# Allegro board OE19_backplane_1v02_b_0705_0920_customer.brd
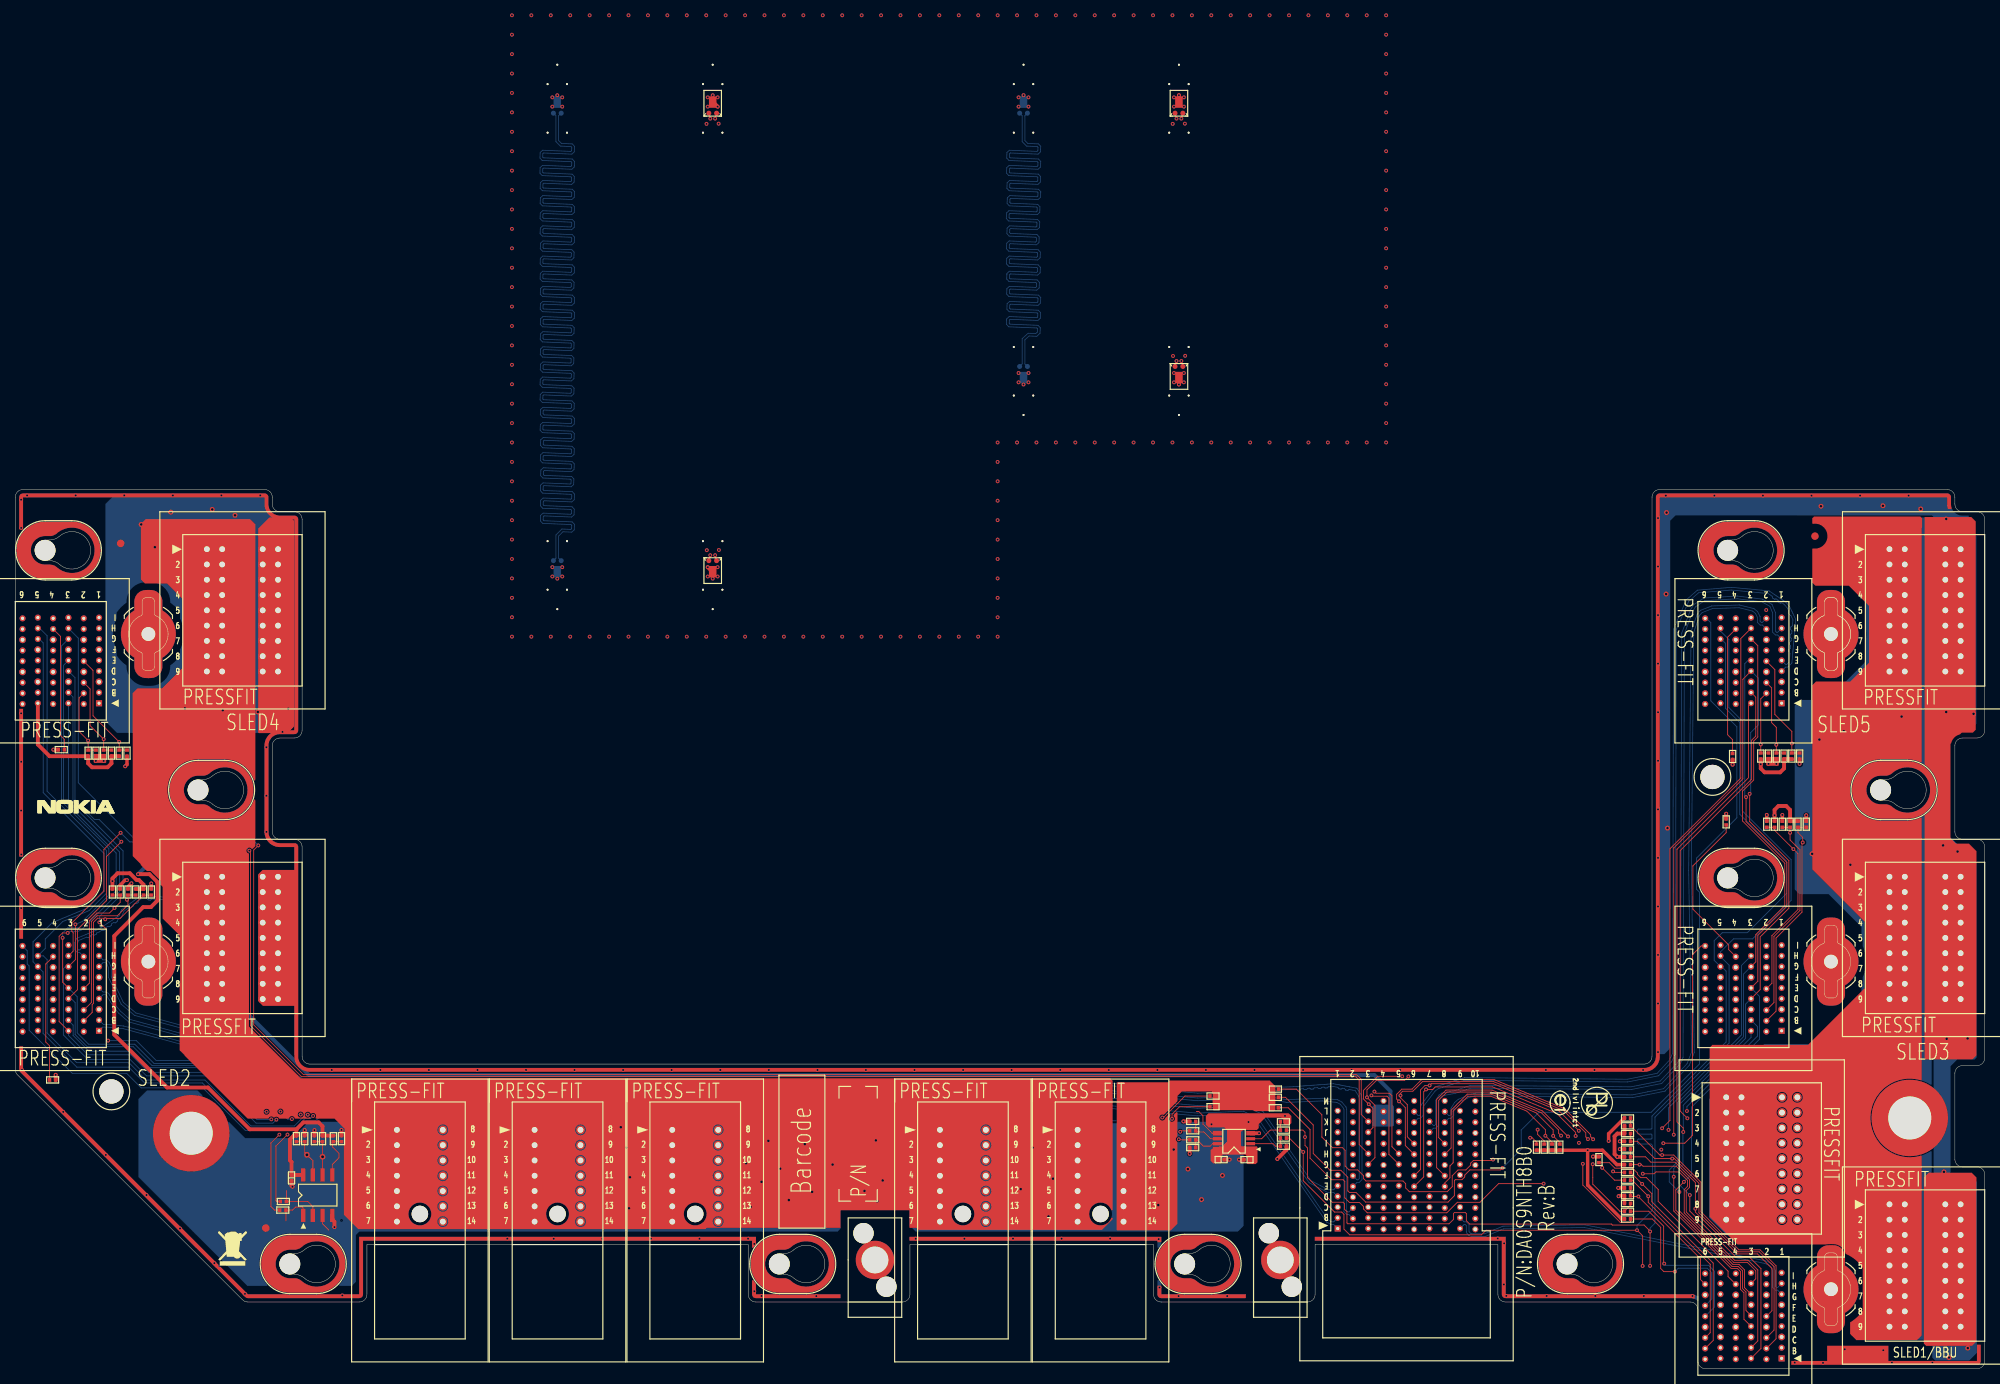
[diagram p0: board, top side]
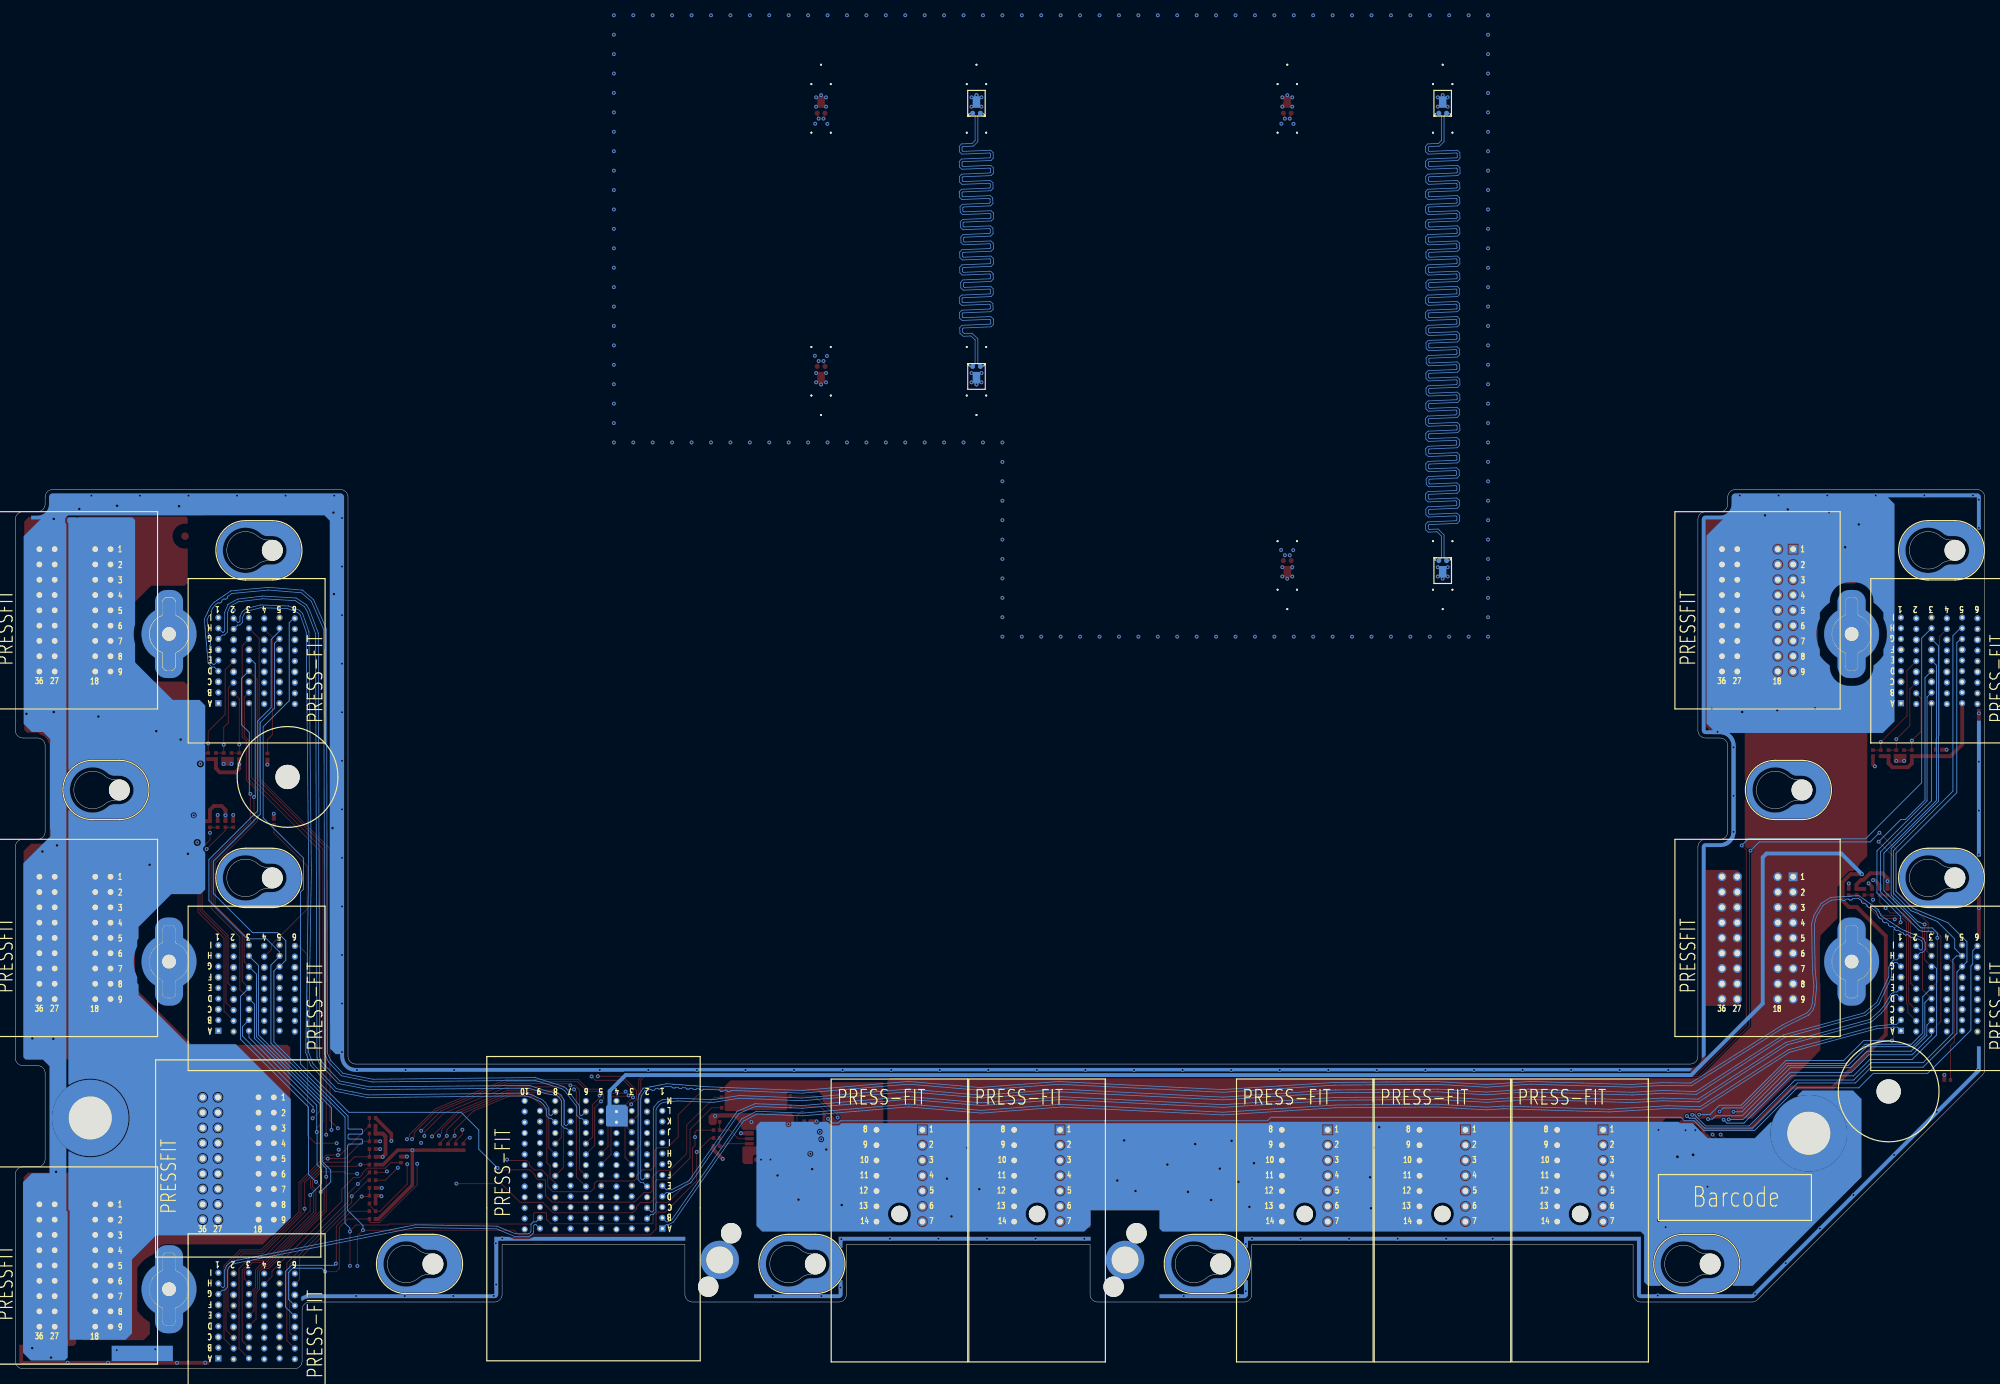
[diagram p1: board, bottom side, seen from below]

Outline 257.5 x 115 mm; copper layers: TOP, GND, IN1, VCC, VCC1, IN2, GND1, BOTTOM. Coordinates in mm from the lower left corner of the outline.

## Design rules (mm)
net group DELTA_L_85_5INCH_BOT_D: nets DELTA_L_85_5INCH_BOT_DN DELTA_L_85_5INCH_BOT_DP
net group DELTA_L_85_5INCH_IN2_D: nets DELTA_L_85_5INCH_IN2_DN DELTA_L_85_5INCH_IN2_DP
net group DELTA_L_85_10INCH_BOT_D: nets DELTA_L_85_10INCH_BOT_DN DELTA_L_85_10INCH_BOT_DP
net group DELTA_L_85_10INCH_IN2_D: nets DELTA_L_85_10INCH_IN2_DN DELTA_L_85_10INCH_IN2_DP
net group SMB_BBU_ALERT_N: nets SMB_BBU_ALERT_N SMB_BBU_ALERT_R_N
net group SMB_PMBUS_BBU_SCL: nets SMB_PMBUS_BBU_SCL SMB_PMBUS_SCL
net group SMB_PMBUS_BBU_SDA: nets SMB_PMBUS_BBU_SDA SMB_PMBUS_SDA
net group SMB_SLED_BUF_SCL: nets SMB_SLED_BUF_SCL SMB_SLED_BUF_SCL_R
net group SMB_SLED_BUF_SDA: nets SMB_SLED_BUF_SDA SMB_SLED_BUF_SDA_R
net group LAN: nets LAN_SLED1_MDIN1 LAN_SLED1_MDIP1 LAN_SLED2_MDIN3 LAN_SLED2_MDIP3 LAN_SLED3_MDIN0 LAN_SLED3_MDIN1 LAN_SLED3_MDIN3 LAN_SLED3_MDIP0 LAN_SLED3_MDIP1 LAN_SLED3_MDIP3 LAN_SLED4_MDIN0 LAN_SLED4_MDIN1 LAN_SLED4_MDIN2 LAN_SLED4_MDIN3 LAN_SLED4_MDIP0 LAN_SLED4_MDIP1 LAN_SLED4_MDIP2 LAN_SLED4_MDIP3 LAN_SLED5_MDIN0 LAN_SLED5_MDIN1 LAN_SLED5_MDIP0 LAN_SLED5_MDIP1
net group P3V3_SLED1: nets P3V3_SLED1 SB_SLED1_ADDR_0 SB_SLED1_ADDR_1 SB_SLED1_ADDR_2
net group P3V3_SLED2: nets P3V3_SLED2 SB_SLED2_ADDR_0 SB_SLED2_ADDR_1 SB_SLED2_ADDR_2
net group P3V3_SLED3: nets P3V3_SLED3 SB_SLED3_ADDR_0 SB_SLED3_ADDR_1 SB_SLED3_ADDR_2
net group P3V3_SLED4: nets P3V3_SLED4 SB_SLED4_ADDR_0 SB_SLED4_ADDR_1 SB_SLED4_ADDR_2
net group P3V3_SLED5: nets P3V3_SLED5 SB_SLED5_ADDR_0 SB_SLED5_ADDR_1 SB_SLED5_ADDR_2
net group SMB_3UBP_TEMP_SCL: nets SMB_3UBP_TEMP_SCL SMB_SLED_COMBINE_SCL SMB_SLED_COMBINE_SCL_R
net group SMB_3UBP_TEMP_SDA: nets SMB_3UBP_TEMP_SDA SMB_SLED_COMBINE_SDA SMB_SLED_COMBINE_SDA_R

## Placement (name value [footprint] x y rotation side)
C1045  0.1UF  [C0402]  36.12 24.96 270 top
C1375  0.1UF  [C0402]  157.66 27.35 0 top
C1377  0.1UF  [C0402]  161.05 27.34 180 top
DM2  -  [WEEE]  26.73 13.47 0 top
DM3  -  [PB-E1_SMALL]  206.79 34.78 270 top
DM4  -  [PNLABEL_15X5]  112.7 21.92 90 top
DM7  -  [BARCODE_20X6]  42.66 19.4 180 bottom
DM8  -  [BARCODE_20X6]  105.85 18.39 90 top
H1  -  [HOLE_C10D5-6B10_NPB]  247.7 32.8 0 top
H2  -  [HOLE_C10D5-6B10_NPB]  23 30.8 0 top
H3  -  [HOLE_C7-5D2-7_4-9B7-5_OB3-5XC3-75N_NPM]  23.9 75.7 90 top
H4  -  [HOLE_C7-5D2-7_4-9B7-5_OB3-5XC3-75N_NPM]  3.9 107.05 90 top
H5  -  [HOLE_C7-5D2-7_4-9B7-5_OB3-5XC3-75N_NPM]  3.9 64.2 90 top
H6  -  [HOLE_C7-5D2-7_4-9B7-5_OB3-5XC3-75N_NPM]  35.9 13.7 90 top
H7  -  [HOLE_C7-5D2-7_4-9B7-5_OB3-5XC3-75N_NPM]  223.9 107.05 90 top
H8  -  [HOLE_C7-5D2-7_4-9B7-5_OB3-5XC3-75N_NPM]  243.9 75.7 90 top
H9  -  [HOLE_C7-5D2-7_4-9B7-5_OB3-5XC3-75N_NPM]  223.9 64.2 90 top
H10  -  [HOLE_C7-5D2-7_4-9B7-5_OB3-5XC3-75N_NPM]  99.9 13.7 90 top
H11  -  [HOLE_C7-5D2-7_4-9B7-5_OB3-5XC3-75N_NPM]  152.9 13.7 90 top
H12  -  [HOLE_C7-5D2-7_4-9B7-5_OB3-5XC3-75N_NPM]  202.9 13.7 90 top
H13  -  [HOLE_TOOLINGD125N_T2-0]  12.56 36.27 0 top
H14  -  [HOLE_TOOLINGD125N_T2-0]  221.9 77.4 0 top
J1  -  [HSD_F36D9_P2_LUV]  245.05 107.2 0 top
J2  -  [HSD_F36D9_P2_LUV]  245.05 21.5 0 top
J3  -  [HSD_F36D9_P2_LUV]  223.7 35.5 0 top
J4  -  [HSD_F36D9_P2_LUV]  25.05 64.35 0 top
J5  -  [HSD_F36D9_P2_LUV]  245.05 64.35 0 top
J6  -  [HSD_F36D9_P2_LUV]  25.05 107.2 0 top
J7  -  [HSD_F54D6_P2W1-4_RDH]  230.95 1.35 180 top
J8  -  [HSD_M120D10H5D_P2W1-4_LDH]  172.9 18.33 180 top
J9  -  [HSD_F54D6_P2W1-4_RDH]  10.95 44.2 180 top
J10  -  [HSD_F54D6_P2W1-4_RDH]  230.95 44.2 180 top
J11  -  [HSD_F54D6_P2W1-4_RDH]  10.95 87.05 180 top
J12  -  [HSD_F54D6_P2W1-4_RDH]  230.95 87.05 180 top
J15  -  [TRIANG_LAUNCH_3PXA]  131.83 165.53 0 bottom
J16  -  [TRIANG_LAUNCH_3PXA]  152.15 129.79 0 top
J21  -  [TRIANG_LAUNCH_3PXA]  131.82 129.79 180 bottom
J22  -  [TRIANG_LAUNCH_3PXA]  152.14 165.53 180 top
J27  -  [TRIANG_LAUNCH_3PXA]  70.86 104.39 180 bottom
J28  -  [TRIANG_LAUNCH_3PXA]  91.18 165.53 180 top
J33  -  [TRIANG_LAUNCH_3PXA]  70.87 165.53 0 bottom
J34  -  [TRIANG_LAUNCH_3PXA]  91.19 104.39 0 top
J37  -  [CON_GUIDE-M1XE]  17.4 53.25 0 top
J38  -  [CON_GUIDE-M1XE]  17.4 96.1 0 top
J39  -  [CON_GUIDE-M1XE]  237.4 10.4 0 top
J40  -  [CON_GUIDE-M1XE]  237.4 53.25 0 top
J41  -  [CON_GUIDE-M1XE]  237.4 96.1 0 top
JP1  -  [HSD_M14]  85.9 31.24 0 top
JP2  -  [HSD_M14]  120.9 31.24 0 top
JP3  -  [HSD_M14]  67.9 31.24 0 top
JP4  -  [HSD_M14]  138.9 31.24 0 top
JP5  -  [CON_GUIDE-FXC]  112.4 14.23 0 top
JP6  -  [CON_GUIDE-FXC]  165.4 14.23 0 top
JP7  -  [HSD_M14]  49.9 31.24 0 top
NOREF  -  []  260.6 232 0 top
NOREF#2  -  []  202.9 13.7 0 top
NOREF#3  -  []  -10 230 0 top
NOREF#4  -  []  258.5 56.87 270 top
NOREF#5  -  []  99.9 13.7 0 top
NOREF#6  -  []  256.5 0 90 top
NOREF#7  -  []  -2 0 0 top
NOREF#8  -  []  237.4 96.1 0 top
NOREF#9  -  []  72.32 40.85 0 top
NOREF#10  -  []  99.9 13.7 0 top
NOREF#11  -  []  223.9 107.05 0 top
NOREF#12  -  []  0.1 140.72 90 top
NOREF#13  -  []  259.6 177.05 90 top
NOREF#14  -  []  -0.9 232 0 top
NOREF#15  -  []  0 39.14 0 top
NOREF#16  -  []  0 0 0 top
NOREF#17  -  []  71.98 191.15 180 top
NOREF#18  -  []  220.1 174.93 90 top
NOREF#19  -  []  135.48 191.15 180 top
NOREF#20  -  []  0.1 178.82 90 top
NOREF#21  -  []  155.31 224.28 180 top
NOREF#22  -  []  17.4 53.25 0 top
NOREF#23  -  []  0 0 0 top
NOREF#24  -  []  3.9 107.05 0 top
NOREF#25  -  []  223.9 107.05 0 top
NOREF#26  -  []  17.4 96.1 0 top
NOREF#27  -  []  237.4 53.25 0 top
NOREF#28  -  []  220.1 132.28 90 top
NOREF#29  -  []  259.6 134.4 90 top
NOREF#30  -  []  45.6 166.85 90 top
NOREF#31  -  []  3.9 64.2 0 top
NOREF#32  -  []  128.6 15.24 0 top
NOREF#33  -  []  258.5 99.52 270 top
NOREF#34  -  []  38.5 99.72 270 top
NOREF#35  -  []  23.9 75.7 0 top
NOREF#36  -  []  157.13 7.72 0 top
NOREF#37  -  []  243.9 75.7 0 top
NOREF#38  -  []  237.4 53.25 0 top
NOREF#39  -  []  85.95 15.24 0 top
NOREF#40  -  []  19.68 116 180 top
NOREF#41  -  []  202.9 13.7 0 top
NOREF#42  -  []  237.4 10.4 0 top
NOREF#43  -  [unnamed#2]  13.77 107.95 0 top
NOREF#44  -  []  123.12 40.85 0 top
NOREF#45  -  []  213 65.15 270 top
NOREF#46  -  []  38.5 57.07 270 top
NOREF#47  -  []  243.9 75.7 0 top
NOREF#48  -  []  237.4 10.4 0 top
NOREF#49  -  [unnamed#2]  235.31 108.9 0 top
NOREF#50  -  []  199.78 7.72 0 top
NOREF#51  -  []  -1 102.62 90 top
NOREF#52  -  []  256.5 0 90 top
NOREF#53  -  []  23.9 75.7 0 top
NOREF#54  -  []  223.9 64.2 0 top
NOREF#55  -  []  56.28 224.28 180 top
NOREF#56  -  []  186.62 40.85 0 top
NOREF#57  -  []  223.9 64.2 0 top
NOREF#58  -  []  45.6 139.3 270 top
NOREF#59  -  []  406.33 171.42 0 top
NOREF#60  -  []  152.9 13.7 0 top
NOREF#61  -  []  259.5 0 0 top
NOREF#62  -  []  17.4 96.1 0 top
NOREF#63  -  []  287.3 400.43 0 top
NOREF#64  -  []  213 92.7 90 top
NOREF#65  -  []  3.9 64.2 0 top
NOREF#66  -  []  237.4 96.1 0 top
NOREF#67  -  []  236.38 116 0 top
NOREF#68  -  []  3.9 107.05 0 top
NOREF#69  -  [unnamed#2]  32.76 18.4 0 top
NOREF#70  -  []  186.28 191.15 180 top
NOREF#71  -  []  152.9 13.7 0 top
NOREF#72  -  []  17.4 53.25 0 top
NOREF#73  -  []  -1 64.52 90 top
R1  4.7K  [R0402]  15.75 62.36 270 top
R2  4.7K  [R0402]  230.02 71.22 270 top
R3  4.7K  [R0402]  9.53 80.52 90 top
R4  4.7K  [R0402]  231.27 80.14 90 top
R5  4.7K  [R0402]  232.28 80.14 90 top
R6  4.7K  [R0402]  13.59 80.52 90 top
R7  1K  [R0402]  10.54 80.52 270 top
R8  4.7K  [R0402]  16.76 62.36 270 top
R9  1K  [R0402]  17.78 62.36 90 top
R10  4.7K  [R0402]  233.09 71.23 270 top
R11  1K  [R0402]  234.17 71.23 90 top
R12  4.7K  [R0402]  232.05 71.22 270 top
R13  4.7K  [R0402]  210.8 30.76 0 top
R14  4.7K  [R0402]  12.7 62.36 270 top
R15  4.7K  [R0402]  210.8 27.71 0 top
R16  4.7K  [R0402]  228.22 80.14 90 top
R17  1K  [R0402]  229.24 80.14 270 top
R18  4.7K  [R0402]  12.57 80.52 90 top
R19  1K  [R0402]  14.73 62.36 90 top
R20  1K  [R0402]  231.04 71.22 90 top
R21  1K  [R0402]  210.8 29.74 180 top
R22  1K  [R0402]  13.72 62.36 90 top
R23  1K  [R0402]  229 71.22 90 top
R24  1K  [R0402]  210.8 28.73 180 top
R25  1K  [R0402]  230.25 80.14 270 top
R26  1K  [R0402]  11.56 80.52 270 top
R27  1K  [R0402]  233.3 80.14 270 top
R28  1K  [R0402]  14.61 80.52 270 top
R29  4.7K  [R0402]  210.8 19.58 0 top
R30  4.7K  [R0402]  201.94 28.98 90 top
R31  4.7K  [R0402]  210.8 22.63 0 top
R32  1K  [R0402]  210.8 23.65 180 top
R33  4.7K  [R0402]  198.89 28.98 90 top
R34  4.7K  [R0402]  200.92 28.98 90 top
R35  4.7K  [R0402]  199.91 28.98 90 top
R36  4.7K  [R0402]  210.8 26.7 0 top
R37  4.7K  [R0402]  210.8 21.62 0 top
R38  0  [R0402]  210.8 20.6 0 top
R39  0  [R0402]  210.8 25.68 0 top
R40  0  [R0402]  210.8 24.66 0 top
R41  100  [R0402]  164.74 34.13 180 top
R42  100  [R0402]  156.6 34.28 0 top
R43  100  [R0402]  164.76 36.57 180 top
R44  100  [R0402]  156.6 35.67 0 top
R45  100  [R0402]  164.75 35.5 180 top
R46  0  [R0402]  153.95 29.94 0 top
R47  0  [R0402]  153.95 31.12 0 top
R48  4.7K  [R0402]  153.95 28.93 0 top
R49  4.7K  [R0402]  153.95 32.35 0 top
R50  4.7K  [R0402]  165.81 29.1 180 top
R51  4.7K  [R0402]  165.81 32.3 180 top
R52  0  [R0402]  165.81 30.17 0 top
R53  0  [R0402]  165.81 31.21 0 top
R54  0  [R0402]  207.07 27.35 90 top
R55  0  [R0402]  4.88 37.78 0 top
R56  0  [R0402]  223.7 71.53 90 top
R57  0  [R0402]  6.01 80.98 180 top
R58  0  [R0402]  224.54 80.08 270 top
R1102  4.7K  [R0402]  41.59 30.09 270 top
R1103  100  [R0402]  42.65 30.09 90 top
R1108  4.7K  [R0402]  40.17 30.09 270 top
R1109  100  [R0402]  39.11 30.09 90 top
R1113  4.7K  [R0402]  36.76 30.09 270 top
R1114  100  [R0402]  37.84 30.09 90 top
R1122  33.2  [R0402]  34.98 20.75 180 top
R1123  33.2  [R0402]  35.05 21.87 180 top
R2297  4.7K  [R0402]  210.8 31.78 0 top
R2298  1K  [R0402]  210.8 32.79 180 top
U31  -  [SOIC8]  39.54 22.7 90 top
U118  -  [TSSOP8_3XB]  159.35 29.76 180 top

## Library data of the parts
C1045 = Q_CAP: alternate symbols: (C0402_OCTAGONXA); part number: Q_CAP_0402-0.1UF,25V,10%,X7R,CH4104K1B00; tolerance: 10%; signal model: DEFAULT_CAPACITOR_100000pF_2_1
C1375 C1377 = Q_CAP: alternate symbols: (C0402_OCTAGONXA); part number: Q_CAP_0402-0.1UF,25V,10%,X7R,CH4104K1B00; tolerance: 10%
DM2 = DUMMY_SYMBOL: part number: DUMMY_SYMBOL-WEEE,MECH,EMPTY,DUMMY2
DM3 = DUMMY_SYMBOL: part number: DUMMY_SYMBOL-PB-E1_SMALL,MECH,EMPTY,DUMMY3
DM4 = DUMMY_SYMBOL: part number: DUMMY_SYMBOL-PCBA_LABEL_15X5,MECH,MECH,DUMMY4
DM7 DM8 = DUMMY_SYMBOL: part number: DUMMY_SYMBOL-BARCODE_20X6,MECH,MECH,DUMMY15
H1 H2 = HOLE: part number: HOLE_TH-EMPTY,HOLE596
H3-H12 = HOLE: part number: HOLE_TH-EMPTY,HOLE1056
H13 H14 = HOLE: part number: HOLE_TH-EMPTY,DUMMY50
J1-J6 = CONN36_10078768001LHLF: part number: CONN36_10078768001LHLF-CONN36_10078768-001LHLF,THLF,IO,DFHS36FS123
J7 J9-J12 = CONN54_10130665102LF: part number: CONN54_10130665102LF-CONN54_10130665-102LF,THLF,IO,DFHS54FS008
J8 = CONN120_10124150102LF: part number: CONN120_10124150102LF-CONN120_10124150-102LF,THLF,IO,DFHDC0MR005
J15 J16 J21 J22 J27 J28 J33 J34 = DELTA_L: part number: DELTA_L-DELTA-L,THLF,EMPTY,TP24
J37-J41 = CONN1_D11402200000Z1: part number: CONN1_D11402200000Z1-CONN1_D11402-200000-Z1,THLF,IO,DFHD01MS073
JP1-JP4 JP7 = CONN14_10028918001LF: part number: CONN14_10028918001LF-CONN14_10028918001LF,THLF,IO,DFPJ14MR000
JP5 JP6 = CONN1_D11403000A00Z1: part number: CONN1_D11403000A00Z1-CONN1_D11403000A00Z1,THLF,IO,DFHS03FR014
R1 R5 R6 R10 R12 R16 R29 R30 R33-R37 R1102 R1108 R2297 = Q_RES: alternate symbols: (SMR0402AW); part number: Q_RES_0402LF-4.7K,1%,1/16W,CHIP,CS24702FB10; tolerance: 1%; signal model: DEFAULT_RESISTOR_4700OHM_2_1
R2-R4 R8 R13-R15 R18 R31 R1113 = Q_RES: alternate symbols: (SMR0402AW); part number: Q_RES_0402LF-4.7K,1%,1/16W,EMPTY,CS24702FB10; tolerance: 1%; signal model: DEFAULT_RESISTOR_4700OHM_2_1
R7 R9 R21-R26 R32 = Q_RES: alternate symbols: (SMR0402AW); part number: Q_RES_0402LF-1K,1%,1/16W,CHIP,TMP_QCS21002FB24; tolerance: 1%; signal model: DEFAULT_RESISTOR_1000.000000OHM_2_1
R11 R17 R19 R20 R27 R28 R2298 = Q_RES: alternate symbols: (SMR0402AW); part number: Q_RES_0402LF-1K,1%,1/16W,EMPTY,TMP_QCS21002FB24; tolerance: 1%; signal model: DEFAULT_RESISTOR_1000.000000OHM_2_1
R38-R40 = Q_RES: alternate symbols: (SMR0402AW); part number: Q_RES_0402LF-0,5%,1/16W,CHIP,CS00002JB38; tolerance: 5%; signal model: DEFAULT_RESISTOR_0.001OHM_2_1
R41-R45 = Q_RES: alternate symbols: (SMR0402AW); part number: Q_RES_0402LF-100,1%,1/16W,CHIP,TMP_QCS11002FB22; tolerance: 1%
R46 R47 R52 R53 = Q_RES: alternate symbols: (SMR0402AW); part number: Q_RES_0402LF-0,5%,1/16W,CHIP,CS00002JB38; tolerance: 5%; signal model: Q_RES_0402LF-0_5%_1/16W_CHIP_CA_0
R48 R49 = Q_RES: alternate symbols: (SMR0402AW); part number: Q_RES_0402LF-4.7K,1%,1/16W,EMPTY,CS24702FB10; tolerance: 1%
R50 R51 = Q_RES: alternate symbols: (SMR0402AW); part number: Q_RES_0402LF-4.7K,1%,1/16W,CHIP,CS24702FB10; tolerance: 1%
R54-R58 = Q_RES: alternate symbols: (SMR0402AW); part number: Q_RES_0402LF-0,5%,1/16W,CHIP,CS00002JB38; tolerance: 5%
R1103 R1109 = Q_RES: alternate symbols: (SMR0402AW); part number: Q_RES_0402LF-100,1%,1/16W,EMPTY,TMP_QCS11002FB22; tolerance: 1%; signal model: DEFAULT_RESISTOR_100OHM_2_1
R1114 = Q_RES: alternate symbols: (SMR0402AW); part number: Q_RES_0402LF-100,1%,1/16W,CHIP,TMP_QCS11002FB22; tolerance: 1%; signal model: DEFAULT_RESISTOR_100OHM_2_1
R1122 R1123 = Q_RES: alternate symbols: (SMR0402AW); part number: Q_RES_0402LF-33.2,1%,1/16W,CHIP,CS03322FB34; tolerance: 1%; signal model: Q_RES_0402LF-33.2_1%_1/16W_CHIA_33.2
U31 = TMP75AIDR: part number: TMP75AIDR_SMLF-TMP75AIDR,IC,TMP_QAL000075061
U118 = PCA9617ADP: part number: PCA9617ADP-PCA9617ADP,SMLF,IC,AL009617K02

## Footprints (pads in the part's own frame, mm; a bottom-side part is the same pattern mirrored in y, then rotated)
BARCODE_20X6
  round 0.102 smd: 1(0,0)
C0402
  rect 0.457x0.508 smd: 1(-0.4,0) 2(0.4,0)
CON_GUIDE-FXC
  round 2.667 hole 2.667 unplated: (-1.5,3.5) (1.5,-3.5)
  round 5.029 hole 3.505: 1(0,0)
CON_GUIDE-M1XE
  custom 1.798x1.798 hole 5.182: G1(0,0)
HOLE_C7-5D2-7_4-9B7-5_OB3-5XC3-75N_NPM
  round 2.718 hole 2.718 unplated: (0,0)
HOLE_C10D5-6B10_NPB
  round 10.008 hole 5.613: 1(0,0)
HOLE_TOOLINGD125N_T2-0
  round 3.175 hole 3.175 unplated: (0,0)
HSD_F36D9_P2_LUV
  rect 1.156x1.156 hole 0.75: 1(0,0)
  round 1.156 hole 0.75: 2(0,-2) 3(0,-4) 4(0,-6) 5(0,-8) 6(0,-10) 7(0,-12) 8(0,-14) 9(0,-16) 10(2,0) 11(2,-2) 12(2,-4) 13(2,-6) 14(2,-8) 15(2,-10) 16(2,-12) 17(2,-14) 18(2,-16) 19(7.3,0) 20(7.3,-2) 21(7.3,-4) 22(7.3,-6) 23(7.3,-8) 24(7.3,-10) 25(7.3,-12) 26(7.3,-14) 27(7.3,-16) 28(9.3,0) 29(9.3,-2) 30(9.3,-4) 31(9.3,-6) 32(9.3,-8) 33(9.3,-10) 34(9.3,-12) 35(9.3,-14) 36(9.3,-16)
HSD_F54D6_P2W1-4_RDH
  rect 0.806x0.806 hole 0.4: A1(0,0)
  round 0.806 hole 0.4: A2(2,0.1) A3(4,0) A4(6,0.1) A5(8,0) A6(10,0.1) B1(0,-1.4) B2(2,-1.3) B3(4,-1.4) B4(6,-1.3) B5(8,-1.4) B6(10,-1.3) C2(2,-2.7) C4(6,-2.7) C6(10,-2.7) D1(0,-4.2) D3(4,-4.2) D5(8,-4.2) E1(0,-5.6) E2(2,-5.5) E3(4,-5.6) E4(6,-5.5) E5(8,-5.6) E6(10,-5.5) F2(2,-6.9) F4(6,-6.9) F6(10,-6.9) G1(0,-8.4) G3(4,-8.4) G5(8,-8.4) H1(0,-9.8) H2(2,-9.7) H3(4,-9.8) H4(6,-9.7) H5(8,-9.8) H6(10,-9.7) I1(0,-11.2) I2(2,-11.1) I3(4,-11.2) I4(6,-11.1) I5(8,-11.2) I6(10,-11.1)
  round 0.906 hole 0.5: C1(0,-2.8) C3(4,-2.8) C5(8,-2.8) D2(2,-4.1) D4(6,-4.1) D6(10,-4.1) F1(0,-7) F3(4,-7) F5(8,-7) G2(2,-8.3) G4(6,-8.3) G6(10,-8.3)
HSD_M14
  round 2.159 hole 2.159 unplated: (3,-11)
  rect 1.156x1.156 hole 0.75: 1(0,0)
  round 1.156 hole 0.75: 2(0,-2) 3(0,-4) 4(0,-6) 5(0,-8) 6(0,-10) 7(0,-12) 8(6,0) 9(6,-2) 10(6,-4) 11(6,-6) 12(6,-8) 13(6,-10) 14(6,-12)
HSD_M120D10H5D_P2W1-4_LDH
  rect 0.8x0.8 hole 0.4: A1(0,0)
  round 0.8 hole 0.5: A2(-2,0.1) A4(-6,0.1) A6(-10,0.1) A8(-14,0.1) A10(-18,0.1) C1(0,-2.8) C3(-4,-2.8) C5(-8,-2.8) C7(-12,-2.8) C9(-16,-2.8) D2(-2,-4.1) D4(-6,-4.1) D6(-10,-4.1) D8(-14,-4.1) D10(-18,-4.1) F1(0,-7) F3(-4,-7) F5(-8,-7) F7(-12,-7) F9(-16,-7) G2(-2,-8.3) G4(-6,-8.3) G6(-10,-8.3) G8(-14,-8.3) G10(-18,-8.3) I1(0,-11.2) I3(-4,-11.2) I5(-8,-11.2) I7(-12,-11.2) I9(-16,-11.2) J2(-2,-12.5) J4(-6,-12.5) J6(-10,-12.5) J8(-14,-12.5) J10(-18,-12.5) L1(0,-15.4) L3(-4,-15.4) L5(-8,-15.4) L7(-12,-15.4) L9(-16,-15.4) MG1(-2,-16.7) MG2(-6,-16.7) MG3(-10,-16.7) MG4(-14,-16.7) MG5(-18,-16.7)
  round 0.8 hole 0.4: A3(-4,0) A5(-8,0) A7(-12,0) A9(-16,0) B1(0,-1.4) B2(-2,-1.3) B3(-4,-1.4) B4(-6,-1.3) B5(-8,-1.4) B6(-10,-1.3) B7(-12,-1.4) B8(-14,-1.3) B9(-16,-1.4) B10(-18,-1.3) C2(-2,-2.7) C4(-6,-2.7) C6(-10,-2.7) C8(-14,-2.7) C10(-18,-2.7) D1(0,-4.2) D3(-4,-4.2) D5(-8,-4.2) D7(-12,-4.2) D9(-16,-4.2) E1(0,-5.6) E2(-2,-5.5) E3(-4,-5.6) E4(-6,-5.5) E5(-8,-5.6) E6(-10,-5.5) E7(-12,-5.6) E8(-14,-5.5) E9(-16,-5.6) E10(-18,-5.5) F2(-2,-6.9) F4(-6,-6.9) F6(-10,-6.9) F8(-14,-6.9) F10(-18,-6.9) G1(0,-8.4) G3(-4,-8.4) G5(-8,-8.4) G7(-12,-8.4) G9(-16,-8.4) H1(0,-9.8) H2(-2,-9.7) H3(-4,-9.8) H4(-6,-9.7) H5(-8,-9.8) H6(-10,-9.7) H7(-12,-9.8) H8(-14,-9.7) H9(-16,-9.8) H10(-18,-9.7) I2(-2,-11.1) I4(-6,-11.1) I6(-10,-11.1) I8(-14,-11.1) I10(-18,-11.1) J1(0,-12.6) J3(-4,-12.6) J5(-8,-12.6) J7(-12,-12.6) J9(-16,-12.6) K1(0,-14) K2(-2,-13.9) K3(-4,-14) K4(-6,-13.9) K5(-8,-14) K6(-10,-13.9) K7(-12,-14) K8(-14,-13.9) K9(-16,-14) K10(-18,-13.9) L2(-2,-15.3) L4(-6,-15.3) L6(-10,-15.3) L8(-14,-15.3) L10(-18,-15.3)
PB-E1_SMALL
  round 0.102 smd: 1(0,0)
PNLABEL_15X5
  round 0.102 smd: 1(0,0)
R0402
  rect 0.457x0.508 smd: 1(-0.4,0) 2(0.4,0)
SOIC8
  rect 1.727x0.559 smd: 1(-2.642,1.905) 2(-2.642,0.635) 3(-2.642,-0.635) 4(-2.642,-1.905) 5(2.642,-1.905) 6(2.642,-0.635) 7(2.642,0.635) 8(2.642,1.905)
TRIANG_LAUNCH_3PXA
  round 0.254 hole 0.991 unplated: (-1.274,3.852) (-1.274,-2.498) (-0.004,-5.038) (1.266,3.852) (1.266,-2.498)
  round 0.66 smd: 1(-0.512,1.301) 2(0.504,1.301)
  rect 0.991x1.499 smd: 3(-0.004,-0.148)
TSSOP8_3XB
  rect 1.168x0.61 smd: 1(-2.175,1.05) 4(-2.175,-1.05) 5(2.175,-1.05) 8(2.175,1.05)
  rect 1.168x0.432 smd: 2(-2.175,0.325) 3(-2.175,-0.325) 6(2.175,-0.325) 7(2.175,0.325)
unnamed#2
  round 0.991 smd: 1(0,0)
WEEE
  round 0.102 smd: 1(0,0)

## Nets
GND: C1045.2(B) C1375.2(B) C1377.2(B) H1.1 H2.1 J1.19 J1.20 J1.21 J1.22 J1.23 J1.24 J1.25 J1.26 J1.27 J1.28 J1.29 J1.30 J1.31 J1.32 J1.33 J1.34 J1.35 J1.36 J2.19 J2.20 J2.21 J2.22 J2.23 J2.24 J2.25 J2.26 J2.27 J2.28 J2.29 J2.30 J2.31 J2.32 J2.33 J2.34 J2.35 J2.36 J3.19 J3.20 J3.21 J3.22 J3.23 J3.24 J3.25 J3.26 J3.27 J3.28 J3.29 J3.30 J3.31 J3.32 J3.33 J3.34 J3.35 J3.36 J4.19 J4.20 J4.21 J4.22 J4.23 J4.24 J4.25 J4.26 J4.27 J4.28 J4.29 J4.30 J4.31 J4.32 J4.33 J4.34 J4.35 J4.36 J5.19 J5.20 J5.21 J5.22 J5.23 J5.24 J5.25 J5.26 J5.27 J5.28 J5.29 J5.30 J5.31 J5.32 J5.33 J5.34 J5.35 J5.36 J6.19 J6.20 J6.21 J6.22 J6.23 J6.24 J6.25 J6.26 J6.27 J6.28 J6.29 J6.30 J6.31 J6.32 J6.33 J6.34 J6.35 J6.36 J7.A2 J7.A4 J7.A6 J7.C1 J7.C3 J7.C5 J7.D2 J7.D4 J7.D6 J7.F1 J7.F3 J7.F5 J7.G2 J7.G4 J7.G6 J7.I1 J7.I3 J7.I5 J8.A2 J8.A4 J8.A6 J8.A8 J8.A10 J8.C1 J8.C3 J8.C5 J8.C7 J8.C9 J8.D2 J8.D4 J8.D6 J8.D8 J8.D10 J8.F1 J8.F3 J8.F5 J8.F7 J8.F9 J8.G2 J8.G4 J8.G6 J8.G8 J8.G10 J8.I1 J8.I3 J8.I5 J8.I7 J8.I9 J8.J2 J8.J4 J8.J6 J8.J8 J8.J10 J8.L1 J8.L3 J8.L5 J8.L7 J8.L9 J8.MG1 J8.MG2 J8.MG3 J8.MG4 J8.MG5 J9.A2 J9.A4 J9.A6 J9.C1 J9.C3 J9.C5 J9.D2 J9.D4 J9.D6 J9.F1 J9.F3 J9.F5 J9.G2 J9.G4 J9.G6 J9.I1 J9.I3 J9.I5 J10.A2 J10.A4 J10.A6 J10.C1 J10.C3 J10.C5 J10.D2 J10.D4 J10.D6 J10.F1 J10.F3 J10.F5 J10.G2 J10.G4 J10.G6 J10.I1 J10.I3 J10.I5 J11.A2 J11.A4 J11.A6 J11.C1 J11.C3 J11.C5 J11.D2 J11.D4 J11.D6 J11.F1 J11.F3 J11.F5 J11.G2 J11.G4 J11.G6 J11.I1 J11.I3 J11.I5 J12.A2 J12.A4 J12.A6 J12.C1 J12.C3 J12.C5 J12.D2 J12.D4 J12.D6 J12.F1 J12.F3 J12.F5 J12.G2 J12.G4 J12.G6 J12.I1 J12.I3 J12.I5 J37.G1 J38.G1 J39.G1 J40.G1 J41.G1 JP1.8 JP1.9 JP1.10 JP1.11 JP1.12 JP1.13 JP1.14 JP2.8 JP2.9 JP2.10 JP2.11 JP2.12 JP2.13 JP2.14 JP3.8 JP3.9 JP3.10 JP3.11 JP3.12 JP3.13 JP3.14 JP4.8 JP4.9 JP4.10 JP4.11 JP4.12 JP4.13 JP4.14 JP5.1 JP6.1 JP7.8 JP7.9 JP7.10 JP7.11 JP7.12 JP7.13 JP7.14 R7.2(B) R9.2(B) R11.2(B) R17.2(B) R19.2(B) R20.2(B) R21.2(B) R22.2(B) R23.2(B) R24.2(B) R25.2(B) R26.2(B) R27.2(B) R28.2(B) R32.2(B) R41.2(B) R42.2(B) R43.2(B) R44.2(B) R45.2(B) R54.2(B) R55.2(B) R56.2(B) R57.2(B) R58.2(B) R1103.2(B) R1109.2(B) R1114.2(B) R2298.2(B) U31.4(GND) U118.4(GND)
P3V3_RMC_STBY: C1045.1(A) C1375.1(A) C1377.1(A) J8.K4 J8.L4 R29.1(A) R30.1(A) R31.1(A) R33.1(A) R34.1(A) R35.1(A) R36.1(A) R37.1(A) R48.1(A) R49.1(A) R50.1(A) R51.1(A) R1102.1(A) R1108.1(A) R1113.1(A) U31.8(VCC) U118.1(VCCA) U118.8(VCCB)
P3V3_SLED1: J7.A5 R13.1(A) R15.1(A) R2297.1(A)
P3V3_SLED2: J9.A5 R1.1(A) R8.1(A) R14.1(A)
P3V3_SLED3: J10.A5 R2.1(A) R10.1(A) R12.1(A)
P3V3_SLED4: J11.A5 R3.1(A) R6.1(A) R18.1(A)
P3V3_SLED5: J12.A5 R4.1(A) R5.1(A) R16.1(A)
P12V_PSU: J1.1 J1.2 J1.3 J1.4 J1.5 J1.6 J1.7 J1.8 J1.9 J1.10 J1.11 J1.12 J1.13 J1.14 J1.15 J1.16 J1.17 J1.18 J2.1 J2.2 J2.3 J2.4 J2.5 J2.6 J2.7 J2.8 J2.9 J2.10 J2.11 J2.12 J2.13 J2.14 J2.15 J2.16 J2.17 J2.18 J3.1 J3.2 J3.3 J3.4 J3.5 J3.6 J3.7 J3.8 J3.9 J3.10 J3.11 J3.12 J3.13 J3.14 J3.15 J3.16 J3.17 J3.18 J4.1 J4.2 J4.3 J4.4 J4.5 J4.6 J4.7 J4.8 J4.9 J4.10 J4.11 J4.12 J4.13 J4.14 J4.15 J4.16 J4.17 J4.18 J5.1 J5.2 J5.3 J5.4 J5.5 J5.6 J5.7 J5.8 J5.9 J5.10 J5.11 J5.12 J5.13 J5.14 J5.15 J5.16 J5.17 J5.18 J6.1 J6.2 J6.3 J6.4 J6.5 J6.6 J6.7 J6.8 J6.9 J6.10 J6.11 J6.12 J6.13 J6.14 J6.15 J6.16 J6.17 J6.18 JP1.1 JP1.2 JP1.3 JP1.4 JP1.5 JP1.6 JP1.7 JP2.1 JP2.2 JP2.3 JP2.4 JP2.5 JP2.6 JP2.7 JP3.1 JP3.2 JP3.3 JP3.4 JP3.5 JP3.6 JP3.7 JP4.1 JP4.2 JP4.3 JP4.4 JP4.5 JP4.6 JP4.7 JP7.1 JP7.2 JP7.3 JP7.4 JP7.5 JP7.6 JP7.7
DELTA_L_85_5INCH_BOT_DN: J15.1 J21.2
DELTA_L_85_5INCH_BOT_DP: J15.2 J21.1
DELTA_L_85_5INCH_IN2_DN: J16.1 J22.2
DELTA_L_85_5INCH_IN2_DP: J16.2 J22.1
DELTA_L_85_10INCH_BOT_DN: J27.1 J33.2
DELTA_L_85_10INCH_BOT_DP: J27.2 J33.1
DELTA_L_85_10INCH_IN2_DN: J28.1 J34.2
DELTA_L_85_10INCH_IN2_DP: J28.2 J34.1
FM_BBU_PRSNT_N: J7.F6 J8.B7 R29.2(B)
FM_BMC_SLED1_READY_N: J7.H3 J8.C8
FM_BMC_SLED2_READY_N: J8.H3 J9.H3
FM_BMC_SLED3_READY_N: J8.F8 J10.H3
FM_BMC_SLED4_READY_N: J8.K3 J11.H3
FM_BMC_SLED5_READY_N: J8.I8 J12.H3
FM_RMC_GPIO_0: J7.D3 J8.F6 J9.D3 J10.D3 J11.D3 J12.D3
FM_RMC_GPIO_1: J7.E3 J8.H6 J9.E3 J10.E3 J11.E3 J12.E3
FM_RMC_GPIO_2: J7.G3 J8.I6 J9.G3 J10.G3 J11.G3 J12.G3
FM_SLED1_PRSNT_N: J7.B3 J8.B8 R36.2(B)
FM_SLED2_PRSNT_N: J8.G3 J9.B3 R35.2(B)
FM_SLED3_PRSNT_N: J8.E8 J10.B3 R34.2(B)
FM_SLED4_PRSNT_N: J8.J3 J11.B3 R33.2(B)
FM_SLED5_PRSNT_N: J8.H8 J12.B3 R30.2(B)
IRQ_RMC_ALERT_N: J7.A3 J8.E6 J9.A3 J10.A3 J11.A3 J12.A3
LAN_SLED1_MDIN0: J7.B1 J8.C10
LAN_SLED1_MDIN1: J7.E1 J8.E10
LAN_SLED1_MDIN2: J7.H1 J8.B9
LAN_SLED1_MDIN3: J7.I2 J8.E9
LAN_SLED1_MDIP0: J7.A1 J8.B10
LAN_SLED1_MDIP1: J7.D1 J8.F10
LAN_SLED1_MDIP2: J7.G1 J8.A9
LAN_SLED1_MDIP3: J7.H2 J8.D9
LAN_SLED2_MDIN0: J8.B1 J9.B1
LAN_SLED2_MDIN1: J8.E1 J9.E1
LAN_SLED2_MDIN2: J8.C2 J9.H1
LAN_SLED2_MDIN3: J8.F2 J9.I2
LAN_SLED2_MDIP0: J8.A1 J9.A1
LAN_SLED2_MDIP1: J8.D1 J9.D1
LAN_SLED2_MDIP2: J8.B2 J9.G1
LAN_SLED2_MDIP3: J8.E2 J9.H2
LAN_SLED3_MDIN0: J8.K10 J10.B1
LAN_SLED3_MDIN1: J8.H10 J10.E1
LAN_SLED3_MDIN2: J8.H9 J10.H1
LAN_SLED3_MDIN3: J8.J9 J10.I2
LAN_SLED3_MDIP0: J8.L10 J10.A1
LAN_SLED3_MDIP1: J8.I10 J10.D1
LAN_SLED3_MDIP2: J8.G9 J10.G1
LAN_SLED3_MDIP3: J8.K9 J10.H2
LAN_SLED4_MDIN0: J8.H1 J11.B1
LAN_SLED4_MDIN1: J8.K1 J11.E1
LAN_SLED4_MDIN2: J8.I2 J11.H1
LAN_SLED4_MDIN3: J8.L2 J11.I2
LAN_SLED4_MDIP0: J8.G1 J11.A1
LAN_SLED4_MDIP1: J8.J1 J11.D1
LAN_SLED4_MDIP2: J8.H2 J11.G1
LAN_SLED4_MDIP3: J8.K2 J11.H2
LAN_SLED5_MDIN0: J8.K5 J12.B1
LAN_SLED5_MDIN1: J8.K6 J12.E1
LAN_SLED5_MDIN2: J8.K7 J12.H1
LAN_SLED5_MDIN3: J8.L8 J12.I2
LAN_SLED5_MDIP0: J8.J5 J12.A1
LAN_SLED5_MDIP1: J8.L6 J12.D1
LAN_SLED5_MDIP2: J8.J7 J12.G1
LAN_SLED5_MDIP3: J8.K8 J12.H2
PD_BBU_A0: J7.H6 R31.2(B) R32.1(A)
PD_SLED1_CHASSIS_INTRUSION: J7.H4 R54.1(A)
PD_SLED1_PRSNT_RETURN: J7.I6 R41.1(A)
PD_SLED2_CHASSIS_INTRUSION: J9.H4 R55.1(A)
PD_SLED2_PRSNT_RETURN: J9.I6 R42.1(A)
PD_SLED3_CHASSIS_INTRUSION: J10.H4 R56.1(A)
PD_SLED3_PRSNT_RETURN: J10.I6 R43.1(A)
PD_SLED4_CHASSIS_INTRUSION: J11.H4 R57.1(A)
PD_SLED4_PRSNT_RETURN: J11.I6 R44.1(A)
PD_SLED5_CHASSIS_INTRUSION: J12.H4 R58.1(A)
PD_SLED5_PRSNT_RETURN: J12.I6 R45.1(A)
SB_SLED1_ADDR_0: J7.B2 R2297.2(B) R2298.1(A)
SB_SLED1_ADDR_1: J7.C2 R13.2(B) R21.1(A)
SB_SLED1_ADDR_2: J7.E2 R15.2(B) R24.1(A)
SB_SLED2_ADDR_0: J9.B2 R8.2(B) R9.1(A)
SB_SLED2_ADDR_1: J9.C2 R1.2(B) R19.1(A)
SB_SLED2_ADDR_2: J9.E2 R14.2(B) R22.1(A)
SB_SLED3_ADDR_0: J10.B2 R10.2(B) R11.1(A)
SB_SLED3_ADDR_1: J10.C2 R12.2(B) R20.1(A)
SB_SLED3_ADDR_2: J10.E2 R2.2(B) R23.1(A)
SB_SLED4_ADDR_0: J11.B2 R3.2(B) R7.1(A)
SB_SLED4_ADDR_1: J11.C2 R18.2(B) R26.1(A)
SB_SLED4_ADDR_2: J11.E2 R6.2(B) R28.1(A)
SB_SLED5_ADDR_0: J12.B2 R16.2(B) R17.1(A)
SB_SLED5_ADDR_1: J12.C2 R4.2(B) R25.1(A)
SB_SLED5_ADDR_2: J12.E2 R5.2(B) R27.1(A)
SMB_3UBP_TEMP_SCL: R1123.1(A) U31.2(SCL)
SMB_3UBP_TEMP_SDA: R1122.1(A) U31.1(SDA)
SMB_BBU_ALERT_N: J8.A7 R37.2(B) R38.1(A)
SMB_BBU_ALERT_R_N: J7.E6 R38.2(B)
SMB_PMBUS_BBU_SCL: J7.B6 R39.2(B)
SMB_PMBUS_BBU_SDA: J7.C6 R40.2(B)
SMB_PMBUS_SCL: J8.D7 R39.1(A)
SMB_PMBUS_SDA: J8.E7 R40.1(A)
SMB_SLED_BUF_SCL: J7.G5 J9.G5 J10.G5 J11.G5 J12.G5 R52.2(B)
SMB_SLED_BUF_SCL_R: R50.2(B) R52.1(A) U118.2(SCLA)
SMB_SLED_BUF_SDA: J7.H5 J9.H5 J10.H5 J11.H5 J12.H5 R53.2(B)
SMB_SLED_BUF_SDA_R: R51.2(B) R53.1(A) U118.3(SDAA)
SMB_SLED_COMBINE_SCL: J8.G5 R46.1(A) R1123.2(B)
SMB_SLED_COMBINE_SCL_R: R46.2(B) R48.2(B) U118.7(SCLB)
SMB_SLED_COMBINE_SDA: J8.H5 R47.1(A) R1122.2(B)
SMB_SLED_COMBINE_SDA_R: R47.2(B) R49.2(B) U118.6(SDAB)
TGND: J15.3 J16.3 J21.3 J22.3 J27.3 J28.3 J33.3 J34.3
TMP75_1_A0: R1113.2(B) R1114.1(A) U31.7(A0)
TMP75_1_A1: R1108.2(B) R1109.1(A) U31.6(A1)
TMP75_1_A2: R1102.2(B) R1103.1(A) U31.5(A2)
TP_BUF_EN: U118.5(EN)
TP_TMP75_1_ALERT: U31.3(ALERT)

Pads without a net: DM2 1; DM3 1; DM4 1; DM7 1; DM8 1; J7 B4 B5 C4 D5 E4 E5 F2 F4 I4; J8 A3 A5 B3 B4 B5 B6 C4 C6 D3 D5 E3 E4 E5 F4 G7 H4 H7 I4; J9 B4 B5 B6 C4 C6 D5 E4 E5 E6 F2 F4 F6 H6 I4; J10 B4 B5 B6 C4 C6 D5 E4 E5 E6 F2 F4 F6 H6 I4; J11 B4 B5 B6 C4 C6 D5 E4 E5 E6 F2 F4 F6 H6 I4; J12 B4 B5 B6 C4 C6 D5 E4 E5 E6 F2 F4 F6 H6 I4; NOREF#43 1; NOREF#49 1; NOREF#69 1

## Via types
v1: diameter 0.508, hole 0.254, TOP to BOTTOM, 448 vias
v2: diameter 0.762, hole 0.381, TOP to BOTTOM, 2 vias
v3: diameter 0.66, hole 0.33, TOP to BOTTOM, 55 vias

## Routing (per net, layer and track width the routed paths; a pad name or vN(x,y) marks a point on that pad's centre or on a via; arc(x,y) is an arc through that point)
GND: length 24.1
  TOP w0.457: R19.2 14.73,63.04 v1(15.18,63.49) ; v1(14.59,63.91) 14.37,63.91 13.72,63.25 R22.2 ; v1(208.33,29.79) 208.33,30.73 210.39,32.79 R2298.2 ; R28.2 14.61,79.04 v1(14.36,78.79) ; R32.2 v1(209.58,23.65) ; R23.2 v1(229,72.43) ; R20.2 v1(231.04,72.43) ; R21.2 v1(209.79,29.74) ; R24.2 v1(209.79,28.73) ; R9.2 v1(17.78,63.48) ; R27.2 v1(233.3,79.12)
  TOP w0.508: v1(41.72,18.52) 41.72,18.53 41.72,19.24 41.45,19.52 U31.4 ; R11.2 v1(234.17,72.39) ; C1375.2 v1(158.76,27.35) ; R55.2 v1(5.28,38.44) ; v1(36.24,23.81) 36.12,23.94 C1045.2 ; R1109.2 v1(39.11,31.2) ; R56.2 v1(223.7,72.59) ; R54.2 v1(206.29,27.75) ; R57.2 v1(4.98,80.98) ; v1(42.65,31.23) R1103.2 ; C1377.2 v1(160,27.34) ; U118.4 v1(162.63,30.81) ; v1(224.54,79.01) R58.2 ; R1114.2 v1(37.84,31.21)
  vias: v1(0.76,113.67) v1(0.76,109.98) v1(0.77,85.73) v1(0.77,79.39) v1(0.77,73) v1(0.78,67.26) v1(0.76,60.25) v1(0.88,39.08) v1(1.55,114.23) v1(6.26,33.59) v1(7.9,114.23) v1(10.54,79.5) v1(11.56,79.5) v1(11.85,27.96) v1(14.25,114.23) v1(17.16,22.72) v1(20.6,114.23) v1(21.54,18.34) v1(26.02,13.81) v1(26.95,114.23) v1(30.03,9.79) v1(32.03,114.23) v1(32.83,81.29) v1(32.83,74.94) v1(32.84,70.22) v1(34.93,83.3) v1(41.38,39.07) v1(42.76,9.59) v1(47.73,39.07) v1(54.08,39.07) v1(60.43,39.07) v1(64.33,17.01) v1(66.78,39.07) v1(70.41,17) v1(73.13,39.07) v1(76.76,17) v1(79.48,39.07) v1(83.11,17) v1(85.83,39.07) v1(89.46,17) v1(92.18,39.07) v1(95.81,17) v1(96.63,16.32) v1(96.63,10.13) v1(97.57,9.51) v1(98.53,39.07) v1(104.73,9.5) v1(104.88,39.07) v1(111.23,39.07) v1(117.58,39.07) v1(117.73,17) v1(123.93,39.07) v1(124.1,17.01) v1(130.28,39.07) v1(130.45,17.01) v1(136.63,39.07) v1(136.8,17.01) v1(142.98,39.07) v1(143.15,17.01) v1(149.33,39.07) v1(149.5,16.95) v1(149.6,10.62) v1(152.11,9.5) v1(155.68,39.07) v1(158.46,9.5) v1(162.03,39.07) v1(168.38,39.07) v1(174.73,39.07) v1(181.08,39.07) v1(193.83,17.04) v1(194.63,11.02) v1(194.67,16.4) v1(194.94,9.52) v1(200.13,39.07) v1(200.23,9.51) v1(204.44,29.54) v1(206.48,39.07) v1(206.58,9.51) v1(212.83,39.07) v1(212.93,9.51) v1(214.78,111.27) v1(214.78,104.92) v1(214.78,98.57) v1(214.78,92.22) v1(214.78,85.87) v1(214.78,79.52) v1(214.78,73.17) v1(214.78,66.82) v1(214.78,60.47) v1(214.78,54.12) v1(214.78,47.77) v1(214.78,41.42) v1(215.21,28.65) v1(215.81,114.21) v1(219.28,9.51) v1(222.16,114.21) v1(228.51,114.21) v1(228.93,99.24) v1(229.24,79.12) v1(230.25,79.12) v1(232.67,0.79) v1(234.86,114.21) v1(236.36,0.76) v1(239.2,2.55) v1(241.21,114.21) v1(244.24,2.42) v1(245.37,0.79) v1(247.56,114.21) v1(250.66,0.78) v3(16.46,110.44) v3(18.25,107.46) v3(20.33,112.04) v3(22.18,86.38) v3(25.75,112.4) v3(27.12,86.14) v3(28.73,111.63) v3(31.71,85.9) v3(35.7,86.32) v3(79.17,31.59) v3(79.89,28.91) v3(80.24,20.99) v3(80.36,25.04) v3(95.55,26.88) v3(96.14,21.17) v3(97.57,24.44) v3(98.47,29.8) v3(100.01,26.17) v3(101.15,22.06) v3(103.23,29.39) v3(104.18,23.13) v3(106.86,26.71) v3(111.03,23.25) v3(112.52,29.86) v3(113.41,24.62) v3(131.46,23.49) v3(133.01,28.91) v3(135.09,19.92) v3(135.69,24.86) v3(149.44,21.4) v3(151.47,28.67) v3(153.31,26.11) v3(155.1,22.12) v3(157.84,25.28) v3(215.84,101.32) v3(215.9,111.98) v3(216.02,70.71) v3(236.09,112.82) v3(244.19,112.88) v3(249.13,112.46) v3(252.05,68.45) v3(252.17,25.75) v3(252.47,111.15) v3(252.47,85.9) v3(252.53,43.14) v3(252.83,1.45) v3(253.95,67.65) v3(255.27,43.2) v3(255.29,2.69) v3(256.04,85.66)
P3V3_RMC_STBY: length 405.2
  TOP w0.457: v1(205.59,28.58) R30.1 R34.1 R35.1 R33.1 ; v1(205.59,28.58) 205.59,24.01 210.02,19.58 R29.1 ; v1(205.59,28.58) 207.51,28.58 209.4,26.7 R36.1 ; v1(209.63,22.56) 209.7,22.63 R31.1 R37.1
  TOP w0.508: R51.1 166.21,32.87 v1(166.01,33.07) ; R49.1 v1(152.74,32.35) ; v1(165.01,27.44) 166.21,28.64 R50.1 ; 36.76,31.32 37.66,32.22 39.66,32.22 40.17,31.71 R1108.1 R1102.1 ; 36.76,31.32 R1113.1 36.41,30.49 35.9,29.99 35.9,27.25 36.12,27.04 C1045.1 36.13,25.34 U31.8 ; 36.76,31.32 30.65,31.32 25.19,36.78 19.86,36.78 12.93,43.71 12.93,56.59 16.72,60.38 17.73,60.38 18.58,61.23 18.58,63.66 17.55,64.69 v1(16.06,64.69) ; R48.1 v1(153.55,28.12)
  IN1 w0.457: J8.K4 178.9,32.12 179.74,31.28 179.74,18.42 180.82,17.35 ; v1(165.01,27.44) 168.09,24.35 168.09,18.81 169.55,17.35 180.82,17.35 ; v1(209.63,22.56) 196.96,22.56 191.75,17.35 180.82,17.35
  IN1 w0.508: v1(153.55,28.12) 154.99,26.68 164.04,26.68 164.8,27.44 v1(165.01,27.44) ; v1(156.41,31.97) 160.95,31.97 v1(161.25,32.27) 162.05,33.07 v1(166.01,33.07)
  IN2 w0.508: v1(152.74,32.35) 152.96,32.58 155.9,32.58 156.41,32.07 v1(156.41,31.97) ; v1(161.25,32.27) 161.25,31.19 v1(165.01,27.44) ; v1(209.63,22.56) 207.79,24.39 205.18,24.39 204.12,25.44 204.12,27.39 205.31,28.58 v1(205.59,28.58)
  BOTTOM w0.508: J8.L4 179.42,33.63 179.8,34.01 179.8,36.3 177.69,38.41 38.37,38.41 29.03,47.76 29.03,66.89 28.52,67.39 18.76,67.39 v1(16.06,64.69)
P3V3_SLED1: length 43.4
  TOP w0.508: R2297.1 R13.1 209.46,30.76 209.1,30.4 209.1,28.07 v1(209.46,27.71) R15.1
  IN1 w0.508: J7.A5 223.72,1.35 224.08,1.71 224.08,12.85 223.23,13.7 219.85,13.7 215.88,17.68 215.88,21.28 214.55,22.61 214.55,25.75 212.56,27.74 209.49,27.74 v1(209.46,27.71)
P3V3_SLED2: length 33.4
  TOP w0.508: R14.1 v1(12.7,63.77) 12.7,64.13 13.37,64.81 14.98,64.81 15.85,63.94 16.15,63.94 16.76,63.33 R8.1 R1.1
  IN1 w0.508: J9.A5 3.87,45.12 3.87,56.34 4.37,56.85 4.61,56.85 6.7,58.94 9.67,58.94 12.7,61.97 v1(12.7,63.77)
P3V3_SLED3: length 44.7
  TOP w0.508: R10.1 232.06,71.63 R12.1 232.05,73.1 231.54,73.6 230.53,73.6 230.02,73.1 v1(230.02,72.39) R2.1
  IN1 w0.508: v1(230.02,72.39) 230.02,72.1 227.86,69.94 221.01,69.94 219.22,68.15 219.22,60.1 221.79,57.53 221.79,45.36 J10.A5
P3V3_SLED4: length 19
  TOP w0.508: J11.A5 2.95,81.65 4.48,80.12 R3.1 9.53,79.18 10.03,78.67 12.06,78.67 12.57,79.18 R18.1 R6.1
P3V3_SLED5: length 17.1
  TOP w0.508: R5.1 R4.1 231.27,78.52 230.76,78.01 228.73,78.01 228.22,78.52 v1(228.22,79.07) R16.1
  IN1 w0.508: J12.A5 222.95,84.33 v1(228.22,79.07)
P12V_PSU:
  vias: v3(234.93,67.35) v3(235.88,82.3) v3(239.07,83.4) v3(239.93,65.92) v3(246.63,85.3)
DELTA_L_85_5INCH_BOT_DN: length 127
  BOTTOM w0.099: J21.2 131.65,131.43 131.65,134.74 132.43,135.44 133.43,135.4 133.64,135.6 133.66,136.03 133.56,136.13 129.89,136.29 129.6,136.61 129.62,137.18 129.63,137.33 129.95,137.63 133.57,137.48 133.68,137.57 133.69,138.01 133.6,138.11 129.94,138.26 129.65,138.58 129.68,139.31 130,139.6 133.6,139.45 133.7,139.55 133.72,139.98 133.62,140.09 129.91,140.24 129.62,140.56 129.65,141.29 129.97,141.58 133.42,141.44 133.52,141.53 133.54,141.97 133.45,142.07 129.92,142.22 129.62,142.54 129.65,143.12 129.65,143.27 129.97,143.56 133.55,143.41 133.65,143.51 133.67,143.94 133.57,144.05 129.89,144.2 129.6,144.52 129.63,145.25 129.95,145.54 133.55,145.39 133.65,145.48 133.67,145.92 133.57,146.02 129.89,146.18 129.6,146.49 129.63,147.22 129.95,147.52 133.39,147.37 133.5,147.47 133.52,147.9 133.42,148.01 129.94,148.15 129.65,148.47 129.68,149.2 130,149.49 133.47,149.35 133.57,149.44 133.59,149.88 133.49,149.98 129.87,150.13 129.57,150.45 129.6,151.18 129.92,151.47 133.5,151.32 133.6,151.42 133.62,151.86 133.52,151.96 129.97,152.11 129.68,152.42 129.7,153.01 129.71,153.15 130.02,153.45 133.6,153.3 133.7,153.39 133.72,153.83 133.62,153.93 129.95,154.08 129.65,154.4 129.68,155.13 130,155.42 133.58,155.28 133.68,155.37 133.7,155.81 133.6,155.91 129.9,156.06 129.61,156.38 129.64,157.11 129.95,157.4 133.6,157.25 133.7,157.35 133.72,157.78 133.62,157.89 129.92,158.04 129.63,158.36 129.66,159.09 129.98,159.38 133.6,159.23 133.7,159.33 133.72,159.76 133.62,159.87 132.23,159.92 131.65,160.5 131.65,163.9 J15.1
DELTA_L_85_5INCH_BOT_DP: length 127
  BOTTOM w0.099: J21.1 132,131.43 132,134.58 132.56,135.09 133.56,135.04 133.99,135.44 134.02,136.16 133.72,136.48 130.06,136.63 129.96,136.74 129.97,137.17 130.08,137.27 133.71,137.12 134.02,137.41 134.05,138.14 133.76,138.46 130.1,138.61 130.01,138.71 130.03,139.15 130.13,139.24 133.73,139.09 134.05,139.39 134.08,140.12 133.79,140.43 130.08,140.59 129.98,140.69 130,141.13 130.1,141.22 133.55,141.08 133.87,141.37 133.9,142.1 133.61,142.42 130.08,142.57 129.98,142.67 130,143.11 130.1,143.2 133.68,143.05 134,143.34 134.03,144.07 133.74,144.39 130.05,144.55 129.96,144.65 129.98,145.08 130.08,145.18 133.68,145.03 134,145.32 134.03,146.05 133.73,146.37 130.05,146.52 129.96,146.63 129.98,147.06 130.08,147.16 133.53,147.01 133.84,147.31 133.88,148.04 133.58,148.35 130.1,148.5 130.01,148.6 130.03,149.04 130.13,149.13 133.6,148.99 133.92,149.28 133.95,150.01 133.66,150.33 130.03,150.48 129.93,150.58 129.95,151.02 130.05,151.11 133.63,150.97 133.95,151.26 133.98,151.99 133.68,152.31 130.13,152.45 130.04,152.56 130.05,152.99 130.16,153.09 133.73,152.94 134.05,153.23 134.07,153.81 134.08,153.96 133.79,154.28 130.11,154.43 130.01,154.53 130.03,154.97 130.13,155.07 133.71,154.92 134.03,155.21 134.06,155.94 133.76,156.26 130.06,156.41 129.96,156.51 129.98,156.95 130.09,157.05 133.73,156.89 134.05,157.19 134.08,157.92 133.78,158.23 130.08,158.39 129.99,158.49 130,158.93 130.11,159.02 133.73,158.87 134.05,159.17 134.06,159.53 134.08,159.89 133.78,160.21 132.38,160.27 132,160.65 132,163.9 J15.2
DELTA_L_85_5INCH_IN2_DN: length 127
  TOP w0.099: J16.1 v1(151.83,131.81) ; J22.2 v1(151.83,163.52)
  IN2 w0.114: v1(151.83,131.81) 151.93,132.06 151.93,134.73 152.19,135.15 152.51,135.35 154.04,135.48 154.18,135.64 154.14,136.06 154.02,136.16 150.25,135.86 149.86,136.19 149.8,136.96 150.13,137.35 154.02,137.67 154.12,137.79 154.09,138.21 153.97,138.32 150.2,138.01 149.81,138.35 149.74,139.12 150.08,139.51 154.01,139.83 154.12,139.95 154.08,140.37 153.96,140.48 150.08,140.16 149.88,140.33 149.69,140.5 149.62,141.27 149.96,141.66 154.05,141.99 154.16,142.12 154.12,142.54 154,142.64 150.12,142.33 149.73,142.66 149.67,143.44 150,143.83 154.05,144.15 154.16,144.28 154.12,144.7 154,144.8 150.08,144.49 149.69,144.82 149.63,145.59 149.96,145.99 154.05,146.32 154.15,146.44 154.12,146.86 153.99,146.96 150.13,146.65 149.73,146.98 149.67,147.76 150,148.15 154.04,148.48 154.18,148.64 154.15,149.02 154.02,149.13 150.19,148.82 149.8,149.15 149.74,149.92 150.07,150.32 153.96,150.63 154.07,150.75 154.03,151.17 153.91,151.28 150.22,150.98 149.83,151.31 149.77,152.09 150.1,152.48 154.09,152.8 154.19,152.92 154.16,153.34 154.03,153.45 150.08,153.13 149.69,153.46 149.63,154.24 149.96,154.63 154.03,154.96 154.14,155.08 154.1,155.5 153.98,155.61 150.18,155.3 149.79,155.63 149.72,156.4 150.06,156.8 153.95,157.11 154.05,157.24 154.02,157.66 153.89,157.76 150.21,157.46 149.82,157.8 149.76,158.57 150.09,158.96 153.9,159.27 154.01,159.39 153.98,159.81 153.85,159.92 152.58,159.82 151.93,160.46 151.93,163.27 v1(151.83,163.52)
DELTA_L_85_5INCH_IN2_DP: length 127
  TOP w0.099: J22.1 v1(152.46,163.52) ; J16.2 v1(152.46,131.81)
  IN2 w0.114: v1(152.46,163.52) 152.36,163.27 152.36,160.64 152.74,160.26 153.99,160.36 154.39,160.02 154.45,159.25 154.12,158.86 150.3,158.55 150.2,158.43 150.23,158.01 150.36,157.9 154.04,158.2 154.43,157.87 154.49,157.09 154.16,156.7 150.27,156.39 150.16,156.26 150.2,155.84 150.32,155.74 154.12,156.05 154.51,155.71 154.58,154.94 154.24,154.55 150.17,154.22 150.07,154.09 150.1,153.67 150.23,153.57 154.18,153.89 154.57,153.56 154.63,152.78 154.3,152.39 150.31,152.07 150.21,151.94 150.24,151.52 150.36,151.42 154.05,151.72 154.44,151.38 154.51,150.61 154.17,150.22 150.28,149.9 150.18,149.78 150.21,149.36 150.33,149.26 154.16,149.57 154.56,149.23 154.62,148.5 154.25,148.06 150.22,147.74 150.11,147.62 150.14,147.2 150.27,147.09 154.14,147.4 154.53,147.07 154.59,146.3 154.26,145.9 150.17,145.57 150.07,145.45 150.1,145.03 150.23,144.93 154.14,145.24 154.53,144.91 154.6,144.14 154.26,143.74 150.21,143.42 150.11,143.29 150.14,142.87 150.27,142.77 154.14,143.08 154.53,142.75 154.6,141.98 154.26,141.58 150.17,141.25 150.06,141.13 150.1,140.71 150.22,140.6 154.1,140.92 154.49,140.58 154.51,140.41 154.56,139.81 154.22,139.42 150.29,139.1 150.18,138.98 150.22,138.56 150.34,138.45 154.11,138.76 154.5,138.42 154.56,137.65 154.23,137.26 150.34,136.94 150.24,136.82 150.27,136.4 150.39,136.3 154.16,136.6 154.55,136.27 154.62,135.49 154.25,135.06 152.65,134.93 152.5,134.84 152.36,134.61 152.36,132.06 v1(152.46,131.81)
DELTA_L_85_10INCH_BOT_DN: length 254
  BOTTOM w0.099: J27.1 71.04,106.03 71.04,108.91 71.6,109.47 72.76,109.43 73.08,109.72 73.11,110.45 72.82,110.77 69.11,110.92 69.02,111.02 69.03,111.46 69.14,111.56 72.74,111.41 73.06,111.7 73.09,112.43 72.8,112.75 69.12,112.9 69.02,113 69.04,113.44 69.14,113.53 72.77,113.38 73.09,113.68 73.12,114.4 72.83,114.72 69.1,114.88 69.01,114.98 69.03,115.42 69.13,115.51 72.69,115.36 73.01,115.66 73.04,116.39 72.74,116.7 69.14,116.85 69.05,116.96 69.07,117.39 69.17,117.49 72.74,117.34 73.06,117.63 73.09,118.36 72.79,118.68 69.1,118.83 69,118.94 69.02,119.37 69.12,119.47 72.74,119.32 73.06,119.61 73.09,120.34 72.8,120.66 69.12,120.81 69.03,120.91 69.05,121.35 69.15,121.44 72.74,121.29 73.06,121.59 73.09,122.32 72.8,122.63 69.07,122.79 68.98,122.89 69,123.33 69.1,123.42 72.77,123.27 73.09,123.56 73.12,124.29 72.82,124.61 69.15,124.76 69,124.92 69.02,125.31 69.12,125.4 72.74,125.25 73.06,125.54 73.09,126.27 72.8,126.59 69.07,126.75 68.97,126.85 68.99,127.28 69.09,127.38 72.71,127.23 73.03,127.52 73.06,128.25 72.77,128.57 69.07,128.72 68.97,128.83 68.99,129.26 69.09,129.36 72.72,129.21 73.04,129.5 73.07,130.23 72.78,130.55 69.1,130.7 69,130.8 69.02,131.24 69.12,131.33 72.69,131.19 73.01,131.48 73.04,132.21 72.75,132.53 69.09,132.68 69,132.78 69.02,133.22 69.12,133.31 72.71,133.16 73.03,133.46 73.06,134.18 72.77,134.5 69.09,134.66 68.99,134.76 69.01,135.2 69.11,135.29 72.73,135.14 73.05,135.43 73.08,136.16 72.79,136.48 69.1,136.63 69,136.74 69.02,137.17 69.12,137.27 72.77,137.12 73.09,137.41 73.12,138.14 72.82,138.46 69.09,138.61 68.99,138.71 69.01,139.15 69.11,139.25 72.77,139.09 73.09,139.39 73.12,140.12 72.83,140.43 69.1,140.59 69,140.69 69.02,141.13 69.12,141.22 72.72,141.07 73.03,141.37 73.06,142.1 72.77,142.41 69.07,142.57 68.98,142.67 68.99,143.11 69.1,143.2 72.77,143.05 73.09,143.34 73.12,144.07 72.82,144.39 69.07,144.55 68.98,144.65 69,145.09 69.1,145.18 72.72,145.03 73.04,145.32 73.07,146.05 72.77,146.37 69.09,146.52 69,146.63 69.02,147.06 69.12,147.16 72.77,147.01 73.08,147.3 73.11,148.03 72.82,148.35 69.07,148.5 68.98,148.6 68.99,149.04 69.1,149.14 72.74,148.98 73.08,149.3 73.11,150.01 72.82,150.32 69.07,150.48 68.97,150.58 68.99,151.02 69.09,151.11 72.77,150.96 73.09,151.25 73.12,151.98 72.83,152.3 69.08,152.46 68.98,152.56 69,153 69.1,153.09 72.77,152.94 73.09,153.23 73.12,153.96 72.83,154.28 69.08,154.43 68.98,154.54 69,154.97 69.1,155.07 72.75,154.92 73.07,155.21 73.1,155.94 72.8,156.26 69.05,156.41 68.95,156.52 68.97,156.95 69.07,157.05 72.77,156.89 73.09,157.19 73.09,157.33 73.09,157.33 73.12,157.92 72.82,158.23 69.05,158.39 68.96,158.49 68.98,158.93 69.08,159.03 72.77,158.87 73.09,159.17 73.12,159.89 72.82,160.21 71.42,160.27 71.04,160.65 71.04,163.9 J33.2
DELTA_L_85_10INCH_BOT_DP: length 254
  BOTTOM w0.099: J33.1 70.69,163.9 70.69,160.5 71.27,159.92 72.66,159.87 72.76,159.76 72.74,159.33 72.64,159.23 68.95,159.38 68.63,159.09 68.6,158.36 68.89,158.04 72.66,157.89 72.76,157.78 72.74,157.35 72.64,157.25 68.94,157.41 68.62,157.11 68.59,156.39 68.89,156.07 72.64,155.91 72.74,155.81 72.72,155.37 72.62,155.28 68.97,155.43 68.65,155.14 68.62,154.41 68.91,154.09 72.66,153.93 72.76,153.83 72.74,153.39 72.64,153.3 68.97,153.45 68.65,153.16 68.62,152.43 68.92,152.11 72.67,151.95 72.76,151.85 72.74,151.41 72.64,151.32 68.96,151.47 68.64,151.18 68.61,150.45 68.91,150.13 72.66,149.98 72.76,149.87 72.74,149.46 72.61,149.34 68.97,149.49 68.65,149.2 68.62,148.47 68.91,148.15 72.66,148 72.76,147.9 72.74,147.46 72.63,147.36 68.99,147.52 68.67,147.22 68.64,146.49 68.93,146.18 72.61,146.02 72.71,145.92 72.69,145.48 72.59,145.39 68.97,145.54 68.65,145.25 68.62,144.52 68.91,144.2 72.66,144.04 72.76,143.94 72.74,143.5 72.64,143.41 68.97,143.56 68.65,143.27 68.62,142.54 68.91,142.22 72.61,142.07 72.71,141.96 72.69,141.53 72.58,141.43 68.99,141.58 68.67,141.29 68.64,140.56 68.93,140.24 72.66,140.09 72.76,139.98 72.74,139.55 72.64,139.45 68.98,139.61 68.66,139.31 68.63,138.58 68.93,138.26 72.66,138.11 72.76,138.01 72.74,137.57 72.64,137.47 68.99,137.63 68.67,137.33 68.64,136.6 68.93,136.29 72.62,136.13 72.72,136.03 72.7,135.59 72.6,135.5 68.98,135.65 68.66,135.36 68.63,134.63 68.93,134.31 72.61,134.16 72.7,134.05 72.68,133.62 72.58,133.52 68.99,133.67 68.67,133.38 68.64,132.65 68.93,132.33 72.59,132.18 72.68,132.08 72.66,131.64 72.56,131.54 68.99,131.69 68.67,131.4 68.64,130.67 68.93,130.35 72.61,130.2 72.71,130.1 72.69,129.66 72.59,129.57 68.96,129.72 68.64,129.42 68.61,128.69 68.9,128.38 72.61,128.22 72.7,128.12 72.68,127.68 72.58,127.59 68.96,127.74 68.64,127.45 68.61,126.72 68.91,126.4 72.63,126.24 72.73,126.14 72.71,125.7 72.61,125.61 68.99,125.76 68.67,125.47 68.65,124.79 68.99,124.42 72.66,124.26 72.76,124.16 72.74,123.73 72.64,123.63 68.97,123.78 68.65,123.49 68.62,122.76 68.91,122.44 72.64,122.29 72.73,122.18 72.71,121.75 72.61,121.65 69.02,121.8 68.7,121.51 68.67,120.78 68.96,120.46 72.64,120.31 72.73,120.21 72.71,119.77 72.61,119.68 68.99,119.83 68.67,119.53 68.64,118.8 68.94,118.49 72.63,118.33 72.73,118.23 72.71,117.79 72.61,117.7 69.04,117.85 68.72,117.55 68.69,116.82 68.98,116.51 72.58,116.36 72.68,116.25 72.66,115.82 72.56,115.72 69,115.87 68.68,115.58 68.65,114.85 68.94,114.53 72.67,114.38 72.76,114.27 72.74,113.84 72.64,113.74 69.01,113.89 68.69,113.6 68.66,112.87 68.96,112.55 72.64,112.4 72.73,112.3 72.71,111.86 72.61,111.76 69.01,111.91 68.69,111.62 68.66,110.89 68.95,110.57 72.66,110.42 72.75,110.32 72.74,109.88 72.63,109.79 71.46,109.83 70.69,109.06 70.69,106.03 J27.2
DELTA_L_85_10INCH_IN2_DN: length 254
  TOP w0.099: J28.1 v1(91.5,163.52) ; J34.2 v1(91.5,106.41)
  IN2 w0.114: v1(91.5,163.52) 91.4,163.27 91.4,160.64 91.78,160.26 93.23,160.37 93.63,160.04 93.69,159.27 93.35,158.87 89.21,158.54 89.11,158.42 89.14,158 89.27,157.89 93.22,158.21 93.61,157.88 93.68,157.1 93.34,156.71 89.24,156.38 89.14,156.26 89.17,155.84 89.3,155.73 93.25,156.05 93.64,155.72 93.71,154.95 93.37,154.55 89.21,154.22 89.11,154.09 89.14,153.67 89.27,153.57 93.22,153.89 93.61,153.56 93.68,152.78 93.34,152.39 89.22,152.06 89.11,151.93 89.14,151.51 89.27,151.41 93.22,151.73 93.61,151.39 93.68,150.62 93.34,150.23 89.21,149.9 89.11,149.77 89.14,149.35 89.27,149.25 93.2,149.57 93.6,149.23 93.66,148.46 93.33,148.07 89.21,147.73 89.1,147.61 89.14,147.19 89.26,147.09 93.24,147.41 93.63,147.07 93.7,146.3 93.36,145.91 89.21,145.57 89.11,145.45 89.14,145.03 89.27,144.93 93.23,145.25 93.62,144.91 93.68,144.14 93.35,143.75 89.21,143.41 89.11,143.29 89.14,142.87 89.27,142.76 93.23,143.09 93.62,142.75 93.68,141.98 93.35,141.59 89.21,141.25 89.1,141.13 89.14,140.71 89.26,140.6 93.23,140.92 93.62,140.59 93.69,139.82 93.35,139.43 89.21,139.09 89.1,138.97 89.14,138.55 89.26,138.44 93.25,138.77 93.64,138.43 93.71,137.66 93.37,137.27 89.2,136.93 89.1,136.81 89.13,136.39 89.26,136.28 93.25,136.6 93.64,136.27 93.7,135.5 93.37,135.1 89.16,134.76 89.06,134.64 89.09,134.22 89.21,134.12 93.23,134.44 93.62,134.11 93.68,133.33 93.35,132.94 89.23,132.61 89.12,132.49 89.16,132.07 89.28,131.96 93.25,132.28 93.64,131.95 93.71,131.18 93.37,130.78 89.21,130.45 89.1,130.32 89.14,129.9 89.26,129.8 93.24,130.12 93.63,129.79 93.7,129.01 93.36,128.62 89.22,128.29 89.11,128.16 89.14,127.74 89.27,127.64 93.27,127.96 93.66,127.63 93.72,126.86 93.39,126.46 89.19,126.12 89.09,126 89.12,125.58 89.25,125.48 93.25,125.8 93.64,125.47 93.7,124.69 93.37,124.3 89.19,123.96 89.09,123.84 89.12,123.42 89.24,123.31 93.25,123.64 93.65,123.3 93.71,122.53 93.37,122.14 89.21,121.8 89.11,121.68 89.14,121.26 89.27,121.16 93.3,121.48 93.69,121.15 93.75,120.38 93.42,119.98 89.25,119.65 89.15,119.52 89.18,119.1 89.31,119 93.27,119.32 93.66,118.98 93.73,118.21 93.39,117.82 89.24,117.48 89.13,117.36 89.17,116.94 89.29,116.84 93.2,117.15 93.58,116.83 93.65,116.04 93.31,115.65 89.22,115.32 89.11,115.2 89.15,114.78 89.27,114.67 93.21,114.99 93.4,114.82 93.6,114.66 93.66,113.88 93.33,113.49 89.27,113.16 89.17,113.04 89.2,112.62 89.32,112.52 93.25,112.83 93.64,112.5 93.7,111.73 93.37,111.33 89.27,111 89.16,110.88 89.2,110.45 89.35,110.32 90.78,110.44 91.4,109.82 91.4,106.66 v1(91.5,106.41)
DELTA_L_85_10INCH_IN2_DP: length 254
  TOP w0.099: J28.2 v1(90.87,163.52) ; J34.1 v1(90.87,106.41)
  IN2 w0.114: v1(90.87,106.41) 90.97,106.66 90.97,109.64 90.62,110 89.21,109.88 88.79,110.24 88.72,111.02 89.06,111.41 93.16,111.75 93.26,111.87 93.23,112.29 93.1,112.39 89.18,112.08 88.79,112.41 88.73,113.18 89.06,113.58 93.12,113.9 93.22,114.03 93.19,114.45 93.06,114.55 89.13,114.23 88.74,114.57 88.72,114.74 88.67,115.34 89.01,115.73 93.1,116.06 93.21,116.19 93.17,116.61 93.06,116.71 89.15,116.4 88.76,116.73 88.69,117.5 89.03,117.9 93.18,118.23 93.29,118.35 93.25,118.77 93.13,118.88 89.16,118.56 88.77,118.89 88.71,119.66 89.04,120.06 93.21,120.39 93.31,120.52 93.28,120.94 93.16,121.04 89.12,120.72 88.73,121.05 88.67,121.82 89,122.21 93.16,122.55 93.27,122.67 93.23,123.09 93.11,123.2 89.1,122.87 88.71,123.21 88.65,123.98 88.98,124.37 93.16,124.71 93.26,124.83 93.23,125.26 93.11,125.36 89.1,125.04 88.71,125.37 88.65,126.14 88.98,126.53 93.18,126.87 93.28,127 93.25,127.42 93.13,127.52 89.13,127.2 88.73,127.53 88.67,128.3 89,128.7 93.15,129.03 93.26,129.16 93.22,129.58 93.1,129.68 89.12,129.36 88.72,129.69 88.66,130.47 89,130.86 93.16,131.19 93.27,131.32 93.23,131.74 93.11,131.84 89.14,131.52 88.75,131.86 88.68,132.63 89.02,133.02 93.14,133.35 93.24,133.48 93.21,133.9 93.09,134 89.07,133.68 88.68,134.01 88.62,134.78 88.95,135.18 93.16,135.52 93.26,135.64 93.23,136.06 93.1,136.16 89.11,135.84 88.72,136.18 88.66,136.95 88.99,137.34 93.16,137.68 93.27,137.8 93.23,138.22 93.11,138.33 89.12,138 88.73,138.34 88.66,139.11 89,139.5 93.14,139.84 93.25,139.96 93.21,140.38 93.09,140.49 89.12,140.16 88.73,140.5 88.66,141.27 89,141.66 93.14,142 93.24,142.12 93.21,142.54 93.09,142.65 89.12,142.33 88.73,142.66 88.67,143.43 89,143.82 93.14,144.16 93.24,144.28 93.21,144.7 93.08,144.81 89.12,144.49 88.73,144.82 88.67,145.59 89,145.99 93.15,146.32 93.26,146.44 93.22,146.86 93.1,146.97 89.12,146.65 88.73,146.98 88.67,147.75 89,148.15 93.11,148.48 93.22,148.6 93.19,149.02 93.06,149.13 89.12,148.81 88.73,149.14 88.72,149.32 88.67,149.91 89,150.31 93.13,150.64 93.24,150.76 93.2,151.18 93.08,151.29 89.13,150.97 88.73,151.3 88.67,152.08 89.01,152.47 93.13,152.8 93.24,152.93 93.2,153.35 93.08,153.45 89.12,153.13 88.73,153.46 88.67,154.24 89,154.63 93.16,154.97 93.27,155.09 93.23,155.51 93.11,155.61 89.16,155.29 88.76,155.63 88.7,156.4 89.03,156.79 93.13,157.12 93.24,157.25 93.2,157.67 93.08,157.77 89.13,157.45 88.73,157.79 88.72,157.96 88.67,158.56 89,158.95 93.14,159.29 93.25,159.41 93.21,159.83 93.09,159.93 91.62,159.82 90.97,160.46 90.97,163.27 v1(90.87,163.52)
FM_BBU_PRSNT_N: length 76.5
  TOP w0.114: v1(204.95,26.8) 204.95,24.03 209.86,19.12 211.08,19.12 211.2,19.23 R29.2 214.04,19.58 215.13,18.49 215.13,13.11 215.54,12.7 v1(216.99,12.7)
  IN1 w0.127: J8.B7 184.11,20.52 184.11,34.43 186.96,37.29 191.99,37.29 196.92,32.35 196.92,28.91 199.03,26.8 v1(204.95,26.8)
  BOTTOM w0.114: J7.F6 221.79,9.09 221.79,12.58 221.23,13.14 217.43,13.14 v1(216.99,12.7)
FM_BMC_SLED1_READY_N: length 71.5
  TOP w0.114: v1(212.8,25.5) 214.27,25.5 214.52,25.75 217.53,25.75 218.64,24.63 218.64,23.84 218.21,23.42 218.21,20.39 224.68,13.91 226.45,13.91 227.56,12.8 227.56,11.76 J7.H3
  IN1 w0.127: J8.C8 187.76,21.9 187.76,34.95 188.81,35.99 191.45,35.99 195.63,31.81 195.63,28.32 198.6,25.34 211.4,25.34 211.56,25.5 v1(212.8,25.5)
FM_BMC_SLED2_READY_N: length 217.9
  TOP w0.114: v1(30.61,67.77) 30.76,67.62 30.76,44.86 37.42,38.2 175.26,38.2 175.71,37.75 175.71,29.32 J8.H3 ; J9.H3 7.56,54.61 7.56,57.04 7.39,57.21 7.39,58.32 11.58,62.5 11.58,67.92 v1(13.77,70.1)
  BOTTOM w0.114: v1(30.61,67.77) 29.47,68.91 14.96,68.91 v1(13.77,70.1)
